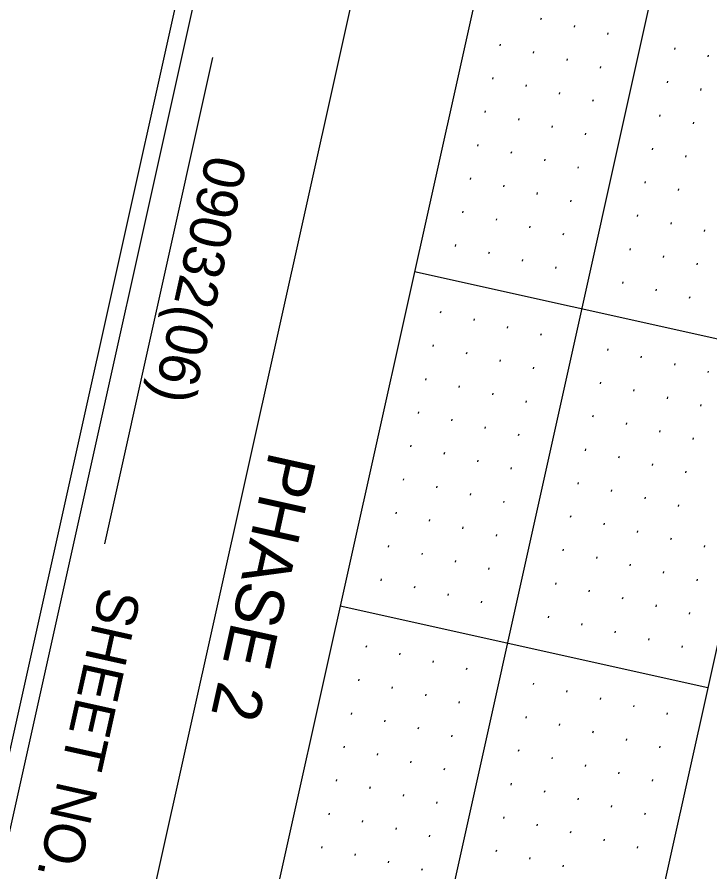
# Model space of a CAD drawing. Extents: x 2149268 to 2150830, y 142155 to 144285.
# Drawn here: x 2149373.2 to 2149474.3, y 142478.9 to 142603.7 of the extents above; entities that cross this region are included whole.
import ezdxf

# ---------------------------------------------------------------- set-up
doc = ezdxf.new("R2010")
doc.units = 0
for name, color, linetype in [('SHT_Plan_Profile_Sheet_Txt', 7, 'Continuous'), ('SHT_Profile_Grid_Major', 7, 'Continuous'), ('SHT_Profile_Grid_Minor', 7, 'Continuous'), ('SHT_Sheet_Border', 7, 'Continuous'), ('SHT_Standard_Sheet_Lines', 7, 'Continuous')]:
    doc.layers.add(name, color=color, linetype=linetype)

msp = doc.modelspace()

# ---------------------------------------------------------------- linework, layer by layer
at = {"layer": 'SHT_Profile_Grid_Major'}
for p, q in [((2149767.6, 143964.37), (2149425.74, 142426.92)), ((2149431.18, 142566.57), (2149484.87, 142554.63)), ((2149420.32, 142517.76), (2149474.01, 142505.82))]:
    msp.add_line(p, q, dxfattribs=at)
at = {"layer": 'SHT_Profile_Grid_Minor'}
for p, q in [((2149449.65, 142603.57), (2149449.59, 142603.32)), ((2149454.53, 142602.48), (2149454.47, 142602.24)), ((2149459.41, 142601.4), (2149459.35, 142601.15)), ((2149443.68, 142599.77), (2149443.63, 142599.53)), ((2149469.17, 142599.22), (2149469.12, 142598.98)), ((2149448.56, 142598.69), (2149448.51, 142598.44)), ((2149474.05, 142598.14), (2149474, 142597.9)), ((2149453.44, 142597.6), (2149453.39, 142597.36)), ((2149458.32, 142596.51), (2149458.27, 142596.27)), ((2149442.6, 142594.89), (2149442.54, 142594.65)), ((2149468.09, 142594.34), (2149468.03, 142594.1)), ((2149447.48, 142593.8), (2149447.42, 142593.56)), ((2149472.97, 142593.26), (2149472.91, 142593.01)), ((2149452.36, 142592.72), (2149452.3, 142592.48)), ((2149457.24, 142591.63), (2149457.18, 142591.39)), ((2149441.51, 142590.01), (2149441.46, 142589.76)), ((2149467, 142589.46), (2149466.95, 142589.22)), ((2149446.39, 142588.92), (2149446.34, 142588.68)), ((2149471.88, 142588.38), (2149471.83, 142588.13)), ((2149451.27, 142587.84), (2149451.22, 142587.59)), ((2149456.15, 142586.75), (2149456.1, 142586.51)), ((2149440.43, 142585.13), (2149440.37, 142584.88)), ((2149465.91, 142584.58), (2149465.86, 142584.34)), ((2149445.31, 142584.04), (2149445.25, 142583.8)), ((2149470.8, 142583.5), (2149470.74, 142583.25)), ((2149450.19, 142582.96), (2149450.13, 142582.71)), ((2149455.07, 142581.87), (2149455.01, 142581.63)), ((2149439.34, 142580.25), (2149439.29, 142580)), ((2149464.83, 142579.7), (2149464.78, 142579.46)), ((2149444.22, 142579.16), (2149444.17, 142578.92)), ((2149449.1, 142578.08), (2149449.05, 142577.83)), ((2149469.71, 142578.62), (2149469.66, 142578.37)), ((2149453.98, 142576.99), (2149453.93, 142576.75)), ((2149438.25, 142575.37), (2149438.2, 142575.12)), ((2149443.14, 142574.28), (2149443.08, 142574.04)), ((2149463.74, 142574.82), (2149463.69, 142574.58)), ((2149448.02, 142573.2), (2149447.96, 142572.95)), ((2149468.62, 142573.74), (2149468.57, 142573.49)), ((2149452.9, 142572.11), (2149452.84, 142571.87)), ((2149473.51, 142572.65), (2149473.45, 142572.41)), ((2149437.17, 142570.49), (2149437.12, 142570.24)), ((2149442.05, 142569.4), (2149442, 142569.16)), ((2149462.66, 142569.94), (2149462.6, 142569.7)), ((2149446.93, 142568.32), (2149446.88, 142568.07)), ((2149467.54, 142568.85), (2149467.49, 142568.61)), ((2149451.81, 142567.23), (2149451.76, 142566.99)), ((2149472.42, 142567.77), (2149472.37, 142567.53)), ((2149461.57, 142565.06), (2149461.52, 142564.82)), ((2149466.45, 142563.97), (2149466.4, 142563.73)), ((2149471.34, 142562.89), (2149471.28, 142562.64)), ((2149435, 142560.72), (2149434.94, 142560.48)), ((2149439.88, 142559.64), (2149439.83, 142559.39)), ((2149444.76, 142558.55), (2149444.71, 142558.31)), ((2149449.64, 142557.47), (2149449.59, 142557.22)), ((2149433.91, 142555.84), (2149433.86, 142555.6)), ((2149438.79, 142554.76), (2149438.74, 142554.51)), ((2149459.4, 142555.3), (2149459.35, 142555.05)), ((2149443.68, 142553.67), (2149443.62, 142553.43)), ((2149464.28, 142554.21), (2149464.23, 142553.97)), ((2149469.16, 142553.13), (2149469.11, 142552.88)), ((2149448.56, 142552.59), (2149448.5, 142552.34)), ((2149474.05, 142552.04), (2149473.99, 142551.8)), ((2149432.83, 142550.96), (2149432.77, 142550.72)), ((2149437.71, 142549.88), (2149437.65, 142549.63)), ((2149458.32, 142550.42), (2149458.26, 142550.17)), ((2149463.2, 142549.33), (2149463.14, 142549.09)), ((2149442.59, 142548.79), (2149442.54, 142548.55)), ((2149468.08, 142548.25), (2149468.03, 142548)), ((2149447.47, 142547.71), (2149447.42, 142547.46)), ((2149472.96, 142547.16), (2149472.91, 142546.92)), ((2149431.74, 142546.08), (2149431.69, 142545.84)), ((2149436.62, 142545), (2149436.57, 142544.75)), ((2149457.23, 142545.54), (2149457.18, 142545.29)), ((2149462.11, 142544.45), (2149462.06, 142544.21)), ((2149441.5, 142543.91), (2149441.45, 142543.67)), ((2149466.99, 142543.37), (2149466.94, 142543.12)), ((2149446.39, 142542.83), (2149446.33, 142542.58)), ((2149471.87, 142542.28), (2149471.82, 142542.04)), ((2149430.66, 142541.2), (2149430.6, 142540.96)), ((2149456.15, 142540.66), (2149456.09, 142540.41)), ((2149435.54, 142540.12), (2149435.48, 142539.87)), ((2149461.03, 142539.57), (2149460.97, 142539.33)), ((2149440.42, 142539.03), (2149440.37, 142538.79)), ((2149465.91, 142538.48), (2149465.85, 142538.24)), ((2149445.3, 142537.95), (2149445.25, 142537.7)), ((2149470.79, 142537.4), (2149470.74, 142537.16)), ((2149429.57, 142536.32), (2149429.52, 142536.08)), ((2149455.06, 142535.77), (2149455.01, 142535.53)), ((2149434.45, 142535.23), (2149434.4, 142534.99)), ((2149459.94, 142534.69), (2149459.89, 142534.45)), ((2149439.33, 142534.15), (2149439.28, 142533.91)), ((2149464.82, 142533.6), (2149464.77, 142533.36)), ((2149444.21, 142533.06), (2149444.16, 142532.82)), ((2149469.7, 142532.52), (2149469.65, 142532.27)), ((2149428.49, 142531.44), (2149428.43, 142531.2)), ((2149453.98, 142530.89), (2149453.92, 142530.65)), ((2149433.37, 142530.35), (2149433.31, 142530.11)), ((2149458.86, 142529.81), (2149458.8, 142529.56)), ((2149438.25, 142529.27), (2149438.19, 142529.02)), ((2149443.13, 142528.18), (2149443.08, 142527.94)), ((2149463.74, 142528.72), (2149463.68, 142528.48)), ((2149468.62, 142527.64), (2149468.56, 142527.39)), ((2149427.4, 142526.56), (2149427.35, 142526.31)), ((2149452.89, 142526.01), (2149452.84, 142525.77)), ((2149473.5, 142526.55), (2149473.45, 142526.31)), ((2149432.28, 142525.47), (2149432.23, 142525.23)), ((2149437.16, 142524.39), (2149437.11, 142524.14)), ((2149457.77, 142524.93), (2149457.72, 142524.68)), ((2149442.04, 142523.3), (2149441.99, 142523.06)), ((2149462.65, 142523.84), (2149462.6, 142523.6)), ((2149467.53, 142522.76), (2149467.48, 142522.51)), ((2149426.32, 142521.68), (2149426.26, 142521.43)), ((2149451.81, 142521.13), (2149451.75, 142520.89)), ((2149472.41, 142521.67), (2149472.36, 142521.43)), ((2149431.2, 142520.59), (2149431.14, 142520.35)), ((2149436.08, 142519.51), (2149436.02, 142519.26)), ((2149456.69, 142520.05), (2149456.63, 142519.8)), ((2149440.96, 142518.42), (2149440.9, 142518.18)), ((2149461.57, 142518.96), (2149461.51, 142518.72)), ((2149466.45, 142517.88), (2149466.39, 142517.63)), ((2149450.72, 142516.25), (2149450.67, 142516.01)), ((2149471.33, 142516.79), (2149471.27, 142516.55)), ((2149455.6, 142515.17), (2149455.55, 142514.92)), ((2149460.48, 142514.08), (2149460.43, 142513.84)), ((2149424.15, 142511.92), (2149424.09, 142511.67)), ((2149465.36, 142513), (2149465.31, 142512.75)), ((2149470.24, 142511.91), (2149470.19, 142511.67)), ((2149429.03, 142510.83), (2149428.97, 142510.59)), ((2149433.91, 142509.75), (2149433.85, 142509.5)), ((2149438.79, 142508.66), (2149438.73, 142508.42)), ((2149423.06, 142507.04), (2149423.01, 142506.79)), ((2149427.94, 142505.95), (2149427.89, 142505.71)), ((2149448.55, 142506.49), (2149448.5, 142506.25)), ((2149432.82, 142504.86), (2149432.77, 142504.62)), ((2149453.43, 142505.4), (2149453.38, 142505.16)), ((2149437.7, 142503.78), (2149437.65, 142503.54)), ((2149458.31, 142504.32), (2149458.26, 142504.08)), ((2149463.19, 142503.23), (2149463.14, 142502.99)), ((2149421.98, 142502.15), (2149421.92, 142501.91)), ((2149468.07, 142502.15), (2149468.02, 142501.9)), ((2149426.86, 142501.07), (2149426.8, 142500.83)), ((2149447.46, 142501.61), (2149447.41, 142501.37)), ((2149431.74, 142499.98), (2149431.68, 142499.74)), ((2149452.35, 142500.52), (2149452.29, 142500.28)), ((2149457.23, 142499.44), (2149457.17, 142499.19)), ((2149436.62, 142498.9), (2149436.56, 142498.65)), ((2149462.11, 142498.35), (2149462.05, 142498.11)), ((2149420.89, 142497.27), (2149420.84, 142497.03)), ((2149466.99, 142497.27), (2149466.93, 142497.02)), ((2149425.77, 142496.19), (2149425.72, 142495.94)), ((2149446.38, 142496.73), (2149446.33, 142496.48)), ((2149451.26, 142495.64), (2149451.21, 142495.4)), ((2149430.65, 142495.1), (2149430.6, 142494.86)), ((2149456.14, 142494.56), (2149456.09, 142494.31)), ((2149435.53, 142494.02), (2149435.48, 142493.77)), ((2149461.02, 142493.47), (2149460.97, 142493.23)), ((2149419.81, 142492.39), (2149419.75, 142492.15)), ((2149465.9, 142492.39), (2149465.85, 142492.14)), ((2149424.69, 142491.31), (2149424.63, 142491.06)), ((2149445.29, 142491.85), (2149445.24, 142491.6)), ((2149450.18, 142490.76), (2149450.12, 142490.52)), ((2149429.57, 142490.22), (2149429.51, 142489.98)), ((2149455.06, 142489.68), (2149455, 142489.43)), ((2149434.45, 142489.14), (2149434.39, 142488.89)), ((2149459.94, 142488.59), (2149459.88, 142488.35)), ((2149418.72, 142487.51), (2149418.67, 142487.27)), ((2149444.21, 142486.97), (2149444.15, 142486.72)), ((2149464.82, 142487.51), (2149464.76, 142487.26)), ((2149423.6, 142486.43), (2149423.55, 142486.18)), ((2149449.09, 142485.88), (2149449.04, 142485.64)), ((2149428.48, 142485.34), (2149428.43, 142485.1)), ((2149453.97, 142484.8), (2149453.92, 142484.55)), ((2149433.36, 142484.26), (2149433.31, 142484.01)), ((2149458.85, 142483.71), (2149458.8, 142483.47)), ((2149417.63, 142482.63), (2149417.58, 142482.39)), ((2149443.12, 142482.09), (2149443.07, 142481.84)), ((2149463.73, 142482.63), (2149463.68, 142482.38)), ((2149422.52, 142481.55), (2149422.46, 142481.3)), ((2149448, 142481), (2149447.95, 142480.76)), ((2149427.4, 142480.46), (2149427.34, 142480.22)), ((2149452.89, 142479.92), (2149452.83, 142479.67)), ((2149432.28, 142479.38), (2149432.22, 142479.13))]:
    msp.add_line(p, q, dxfattribs=at)
at = {"layer": 'SHT_Sheet_Border'}
for points in [[(2150726.67, 143751.11), (2150384.81, 142213.66), (2149359.84, 142441.57), (2149701.71, 143979.02)], [(2149437.43, 142675.3), (2149415.46, 142680.19), (2149362.83, 142443.47), (2149384.79, 142438.59)], [(2149515.24, 142599.1), (2149495.72, 142603.44), (2149463.16, 142457.01), (2149482.68, 142452.67)]]:
    msp.add_lwpolyline(points, close=True, dxfattribs=at)
msp.add_lwpolyline([(2149433.9, 142694.01), (2149458.31, 142688.59), (2149409.47, 142468.95)], dxfattribs=at)
at = {"layer": 'SHT_Standard_Sheet_Lines'}
msp.add_line((2149401.69, 142597.8), (2149385.91, 142526.82), dxfattribs=at)

# ---------------------------------------------------------------- texts
at = {"layer": 'SHT_Plan_Profile_Sheet_Txt'}
for s, height, p in [('09032(06)', 6, (2149400.89, 142583.82)), ('PHASE 2', 7, (2149410.04, 142540.5)), ('SHEET NO.', 6, (2149385.44, 142520.7))]:
    msp.add_text(s, height=height, rotation=257.4638, dxfattribs=at).set_placement(p)

doc.saveas('drawing.dxf')
